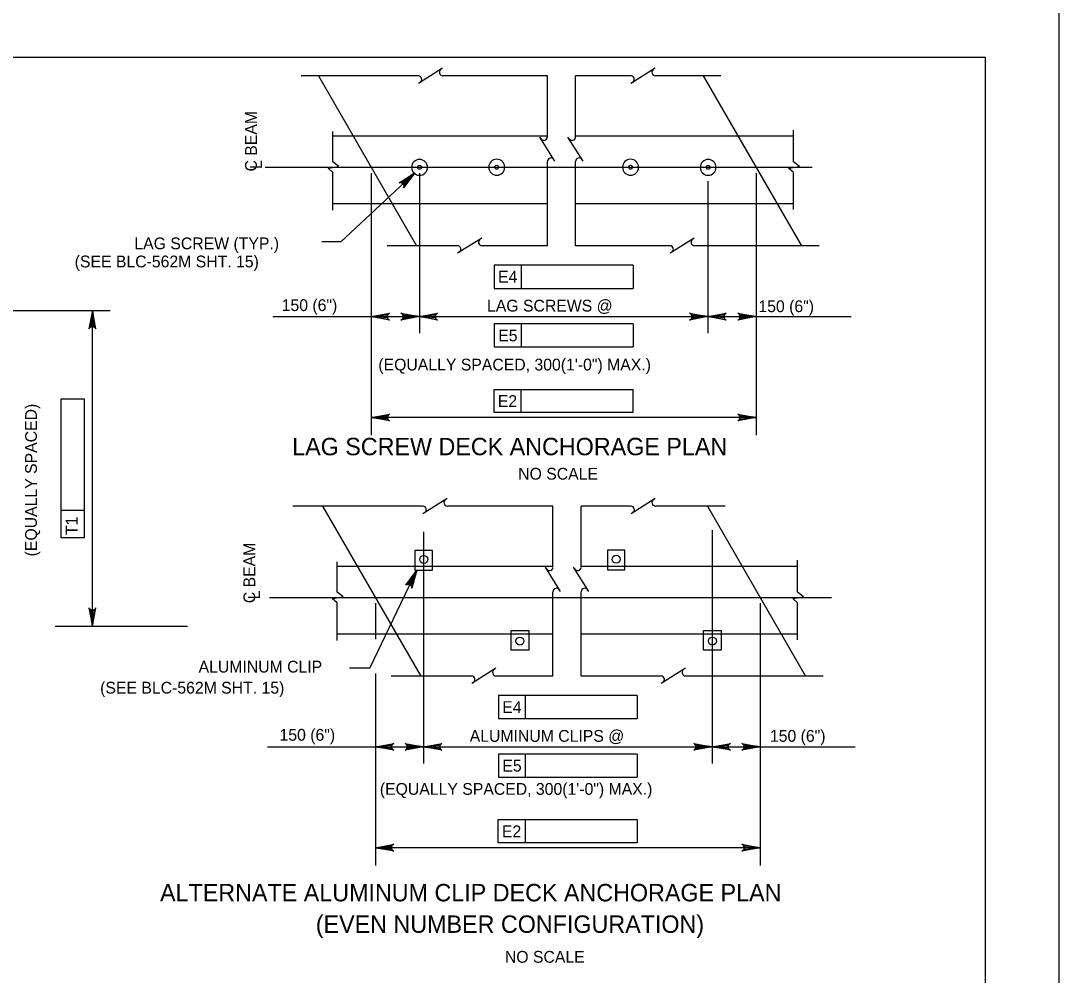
# Model space of a CAD drawing. Extents: x -13 to 81, y -176 to 0.
# Drawn here: x 57.44 to 68, y -120.08 to -110.38 of the extents above; entities that cross this region are included whole.
import ezdxf

# ---------------------------------------------------------------- set-up
doc = ezdxf.new("R2010")
doc.units = 0
for name, color, linetype in [('Level 1', 7, 'Continuous'), ('Level 2', 7, 'Continuous'), ('Level 3', 7, 'Continuous'), ('Level 4', 7, 'Continuous'), ('Level 63', 7, 'Continuous'), ('Level 8', 7, 'Continuous'), ('Level 9', 7, 'Continuous')]:
    doc.layers.add(name, color=color, linetype=linetype)

# ---------------------------------------------------------------- blocks, each defined once
blk = doc.blocks.new('B')
at = {"layer": 'Level 3'}
blk.add_circle((0, 0), 0.107, dxfattribs=at)
for start, end in [(0, 180), (180, 0)]:
    blk.add_arc((0, 0), 0.026, start, end, dxfattribs=at)

msp = doc.modelspace()

# ---------------------------------------------------------------- linework, layer by layer
at = {"layer": 'Level 1'}
msp.add_lwpolyline([(35.75, -131.25), (67.25, -131.25), (67.25, -110.75), (35.75, -110.75)], close=True, dxfattribs=at)
at = {"layer": 'Level 2'}
for p, q in [((60.466, -110.934), (61.465, -112.662)), ((64.379, -110.934), (65.378, -112.662)), ((60.508, -115.308), (61.507, -117.036)), ((64.422, -115.308), (65.42, -117.036))]:
    msp.add_line(p, q, dxfattribs=at)
at = {"layer": 'Level 3'}
for p, q in [((61.73, -110.857), (61.484, -111.012)), ((63.891, -110.857), (63.645, -111.012)), ((61.484, -110.934), (60.291, -110.934)), ((62.795, -110.934), (61.733, -110.934)), ((62.795, -111.557), (62.795, -110.934)), ((63.081, -111.557), (63.081, -110.934)), ((63.645, -110.934), (63.081, -110.934)), ((64.559, -110.934), (63.894, -110.934)), ((60.614, -111.81), (60.614, -111.501)), ((65.297, -111.81), (65.297, -111.486)), ((62.795, -111.548), (60.614, -111.548)), ((62.872, -111.803), (62.717, -111.557)), ((63.158, -111.803), (63.003, -111.557)), ((65.297, -111.548), (63.081, -111.548)), ((60.675, -111.857), (60.614, -111.81)), ((62.795, -112.662), (62.795, -111.806)), ((63.081, -112.662), (63.081, -111.806)), ((65.358, -111.857), (65.297, -111.81)), ((60.565, -111.874), (60.675, -111.857)), ((60.614, -111.918), (60.565, -111.874)), ((60.614, -112.302), (60.614, -111.918)), ((65.248, -111.874), (65.358, -111.857)), ((65.297, -111.918), (65.248, -111.874)), ((65.297, -112.295), (65.297, -111.918)), ((60.614, -112.233), (62.795, -112.233)), ((63.081, -112.233), (65.297, -112.233)), ((61.882, -112.662), (61.164, -112.662)), ((62.128, -112.584), (61.882, -112.739)), ((62.795, -112.662), (62.131, -112.662)), ((64.043, -112.662), (63.081, -112.662)), ((64.289, -112.584), (64.043, -112.739)), ((65.558, -112.662), (64.292, -112.662)), ((61.53, -115.308), (60.208, -115.308)), ((61.776, -115.231), (61.53, -115.386)), ((62.852, -115.308), (61.779, -115.308)), ((62.852, -115.931), (62.852, -115.308)), ((63.138, -115.931), (63.138, -115.308)), ((63.646, -115.308), (63.138, -115.308)), ((63.892, -115.231), (63.646, -115.386)), ((64.602, -115.308), (63.895, -115.308)), ((60.656, -116.184), (60.656, -115.875)), ((62.852, -115.922), (60.656, -115.922)), ((62.929, -116.177), (62.775, -115.931)), ((63.216, -116.177), (63.061, -115.931)), ((65.339, -115.922), (63.138, -115.922)), ((65.339, -116.184), (65.339, -115.86)), ((60.608, -116.248), (60.718, -116.231)), ((60.656, -116.292), (60.608, -116.248)), ((60.718, -116.231), (60.656, -116.184)), ((62.852, -117.036), (62.852, -116.18)), ((63.138, -117.036), (63.138, -116.18)), ((65.29, -116.248), (65.401, -116.231)), ((65.339, -116.292), (65.29, -116.248)), ((65.401, -116.231), (65.339, -116.184)), ((60.656, -116.676), (60.656, -116.292)), ((65.339, -116.669), (65.339, -116.292)), ((60.656, -116.607), (62.852, -116.607)), ((63.138, -116.607), (65.339, -116.607)), ((62.271, -116.958), (62.025, -117.113)), ((64.198, -116.958), (63.952, -117.113)), ((62.025, -117.036), (61.206, -117.036)), ((62.852, -117.036), (62.274, -117.036)), ((63.952, -117.036), (63.138, -117.036)), ((65.6, -117.036), (64.201, -117.036))]:
    msp.add_line(p, q, dxfattribs=at)
for centre in [(61.538, -115.851), (63.494, -115.849), (62.516, -116.681), (64.473, -116.681)]:
    msp.add_circle(centre, 0.0407, dxfattribs=at)
for centre, start, end in [((61.733, -110.898), 120, 270), ((63.894, -110.898), 120, 270), ((61.481, -110.971), 302.1328, 84.6714), ((63.642, -110.971), 302.1328, 84.6714), ((62.758, -111.554), 212.1328, 354.6714), ((63.045, -111.554), 212.1328, 354.6714), ((62.831, -111.806), 30, 180), ((63.117, -111.806), 30, 180), ((61.879, -112.698), 302.1328, 84.6714), ((62.131, -112.625), 120, 270), ((64.04, -112.698), 302.1328, 84.6714), ((64.292, -112.625), 120, 270), ((61.527, -115.345), 302.1328, 84.6714), ((61.779, -115.272), 120, 270), ((63.643, -115.345), 302.1328, 84.6714), ((63.895, -115.272), 120, 270), ((62.816, -115.928), 212.1328, 354.6714), ((63.102, -115.928), 212.1328, 354.6714), ((62.888, -116.18), 30, 180), ((63.175, -116.18), 30, 180), ((62.274, -116.999), 120, 270), ((64.201, -116.999), 120, 270), ((62.022, -117.072), 302.1328, 84.6714), ((63.949, -117.072), 302.1328, 84.6714)]:
    msp.add_arc(centre, 0.0364, start, end, dxfattribs=at)
at = {"layer": 'Level 4'}
for p, q in [((59.926, -111.864), (65.488, -111.864)), ((60.693, -112.621), (60.502, -112.621)), ((62.254, -112.858), (62.254, -113.095)), ((62.53, -112.858), (62.254, -112.858)), ((63.666, -112.858), (62.53, -112.858)), ((62.53, -113.095), (62.53, -112.858)), ((63.666, -112.858), (63.666, -113.095)), ((61.003, -113.034), (61.003, -114.588)), ((62.254, -113.095), (63.666, -113.095)), ((64.917, -113.034), (64.917, -114.588)), ((54.307, -113.32), (58.348, -113.32)), ((58.168, -116.53), (58.168, -113.32)), ((61.003, -113.382), (61.493, -113.382)), ((64.428, -113.382), (64.917, -113.382)), ((62.254, -113.455), (62.254, -113.691)), ((62.53, -113.455), (62.254, -113.455)), ((62.53, -113.691), (62.53, -113.455)), ((63.666, -113.455), (62.53, -113.455)), ((63.666, -113.455), (63.666, -113.691)), ((62.254, -113.691), (63.666, -113.691)), ((62.253, -114.122), (62.528, -114.122)), ((62.253, -114.358), (62.253, -114.122)), ((62.528, -114.358), (62.528, -114.122)), ((62.528, -114.122), (63.665, -114.122)), ((63.665, -114.122), (63.665, -114.358)), ((57.849, -114.219), (58.085, -114.219)), ((57.849, -115.355), (57.849, -114.219)), ((58.085, -114.219), (58.085, -115.631)), ((63.665, -114.358), (62.253, -114.358)), ((64.917, -114.408), (61.003, -114.408)), ((57.849, -115.631), (57.849, -115.355)), ((58.085, -115.355), (57.849, -115.355)), ((58.085, -115.631), (57.849, -115.631)), ((60.989, -116.956), (61.467, -115.96)), ((59.969, -116.238), (65.685, -116.238)), ((57.789, -116.53), (59.135, -116.53)), ((60.989, -116.956), (60.782, -116.956)), ((62.297, -117.233), (62.297, -117.469)), ((62.572, -117.233), (62.297, -117.233)), ((62.572, -117.469), (62.572, -117.233)), ((63.709, -117.233), (62.572, -117.233)), ((63.709, -117.233), (63.709, -117.469)), ((61.046, -117.408), (61.046, -118.962)), ((64.959, -117.408), (64.959, -118.962)), ((62.297, -117.469), (63.709, -117.469)), ((61.046, -117.756), (61.535, -117.756)), ((62.297, -117.829), (62.297, -118.065)), ((62.572, -117.829), (62.297, -117.829)), ((63.709, -117.829), (62.572, -117.829)), ((62.572, -118.065), (62.572, -117.829)), ((63.709, -117.829), (63.709, -118.065)), ((64.47, -117.756), (64.959, -117.756)), ((62.297, -118.065), (63.709, -118.065)), ((62.295, -118.496), (62.571, -118.496)), ((62.295, -118.732), (62.295, -118.496)), ((62.571, -118.732), (62.571, -118.496)), ((62.571, -118.496), (63.707, -118.496)), ((63.707, -118.496), (63.707, -118.732)), ((64.959, -118.782), (61.046, -118.782)), ((63.707, -118.732), (62.295, -118.732))]:
    msp.add_line(p, q, dxfattribs=at)
for points in [[(61.446, -111.922), (60.693, -112.621)], [(61.446, -111.922), (61.333, -112.074), (61.337, -112.057), (61.334, -112.043), (61.327, -112.032), (61.317, -112.025), (61.303, -112.02), (61.286, -112.023), (61.446, -111.922), (61.303, -112.02), (61.317, -112.025), (61.446, -111.922), (61.327, -112.032), (61.334, -112.043), (61.446, -111.922), (61.337, -112.057)], [(58.168, -113.32), (58.133, -113.507), (58.143, -113.493), (58.156, -113.485), (58.168, -113.483), (58.181, -113.485), (58.193, -113.493), (58.203, -113.507), (58.168, -113.32), (58.193, -113.493), (58.181, -113.485), (58.168, -113.32), (58.168, -113.483), (58.156, -113.485), (58.168, -113.32), (58.143, -113.493)], [(61.003, -113.382), (61.19, -113.347), (61.176, -113.357), (61.168, -113.369), (61.166, -113.382), (61.168, -113.394), (61.176, -113.407), (61.19, -113.417), (61.003, -113.382), (61.176, -113.407), (61.168, -113.394), (61.003, -113.382), (61.166, -113.382), (61.168, -113.369), (61.003, -113.382), (61.176, -113.357)], [(61.493, -113.382), (61.306, -113.417), (61.321, -113.407), (61.328, -113.394), (61.33, -113.382), (61.328, -113.369), (61.321, -113.357), (61.306, -113.347), (61.493, -113.382), (61.321, -113.357), (61.328, -113.369), (61.493, -113.382), (61.33, -113.382), (61.328, -113.394), (61.493, -113.382), (61.321, -113.407)], [(61.493, -113.382), (61.679, -113.347), (61.665, -113.357), (61.657, -113.369), (61.655, -113.382), (61.657, -113.394), (61.665, -113.407), (61.679, -113.417), (61.493, -113.382), (61.665, -113.407), (61.657, -113.394), (61.493, -113.382), (61.655, -113.382), (61.657, -113.369), (61.493, -113.382), (61.665, -113.357)], [(64.428, -113.382), (64.241, -113.417), (64.256, -113.407), (64.263, -113.394), (64.265, -113.382), (64.263, -113.369), (64.256, -113.357), (64.241, -113.347), (64.428, -113.382), (64.256, -113.357), (64.263, -113.369), (64.428, -113.382), (64.265, -113.382), (64.263, -113.394), (64.428, -113.382), (64.256, -113.407)], [(64.428, -113.382), (64.614, -113.347), (64.6, -113.357), (64.592, -113.369), (64.59, -113.382), (64.592, -113.394), (64.6, -113.407), (64.614, -113.417), (64.428, -113.382), (64.6, -113.407), (64.592, -113.394), (64.428, -113.382), (64.59, -113.382), (64.592, -113.369), (64.428, -113.382), (64.6, -113.357)], [(64.917, -113.382), (64.73, -113.417), (64.745, -113.407), (64.752, -113.394), (64.754, -113.382), (64.752, -113.369), (64.745, -113.357), (64.73, -113.347), (64.917, -113.382), (64.745, -113.357), (64.752, -113.369), (64.917, -113.382), (64.754, -113.382), (64.752, -113.394), (64.917, -113.382), (64.745, -113.407)], [(61.003, -114.408), (61.19, -114.373), (61.176, -114.383), (61.168, -114.395), (61.166, -114.408), (61.168, -114.42), (61.176, -114.433), (61.19, -114.443), (61.003, -114.408), (61.176, -114.433), (61.168, -114.42), (61.003, -114.408), (61.166, -114.408), (61.168, -114.395), (61.003, -114.408), (61.176, -114.383)], [(64.917, -114.408), (64.73, -114.443), (64.745, -114.433), (64.752, -114.42), (64.754, -114.408), (64.752, -114.395), (64.745, -114.383), (64.73, -114.373), (64.917, -114.408), (64.745, -114.383), (64.752, -114.395), (64.917, -114.408), (64.754, -114.408), (64.752, -114.42), (64.917, -114.408), (64.745, -114.433)], [(61.467, -115.96), (61.418, -116.143), (61.415, -116.126), (61.407, -116.114), (61.396, -116.107), (61.384, -116.103), (61.37, -116.105), (61.355, -116.113), (61.467, -115.96), (61.37, -116.105), (61.384, -116.103), (61.467, -115.96), (61.396, -116.107), (61.407, -116.114), (61.467, -115.96), (61.415, -116.126)], [(58.168, -116.53), (58.203, -116.344), (58.193, -116.358), (58.181, -116.366), (58.168, -116.368), (58.156, -116.366), (58.143, -116.358), (58.133, -116.344), (58.168, -116.53), (58.143, -116.358), (58.156, -116.366), (58.168, -116.53), (58.168, -116.368), (58.181, -116.366), (58.168, -116.53), (58.193, -116.358)], [(61.046, -117.756), (61.232, -117.721), (61.218, -117.731), (61.211, -117.743), (61.208, -117.756), (61.211, -117.768), (61.218, -117.781), (61.232, -117.791), (61.046, -117.756), (61.218, -117.781), (61.211, -117.768), (61.046, -117.756), (61.208, -117.756), (61.211, -117.743), (61.046, -117.756), (61.218, -117.731)], [(61.535, -117.756), (61.349, -117.791), (61.363, -117.781), (61.37, -117.768), (61.373, -117.756), (61.37, -117.743), (61.363, -117.731), (61.349, -117.721), (61.535, -117.756), (61.363, -117.731), (61.37, -117.743), (61.535, -117.756), (61.373, -117.756), (61.37, -117.768), (61.535, -117.756), (61.363, -117.781)], [(61.535, -117.756), (61.721, -117.721), (61.707, -117.731), (61.7, -117.743), (61.698, -117.756), (61.7, -117.768), (61.707, -117.781), (61.721, -117.791), (61.535, -117.756), (61.707, -117.781), (61.7, -117.768), (61.535, -117.756), (61.698, -117.756), (61.7, -117.743), (61.535, -117.756), (61.707, -117.731)], [(64.47, -117.756), (64.284, -117.791), (64.298, -117.781), (64.305, -117.768), (64.308, -117.756), (64.305, -117.743), (64.298, -117.731), (64.284, -117.721), (64.47, -117.756), (64.298, -117.731), (64.305, -117.743), (64.47, -117.756), (64.308, -117.756), (64.305, -117.768), (64.47, -117.756), (64.298, -117.781)], [(64.47, -117.756), (64.657, -117.721), (64.642, -117.731), (64.635, -117.743), (64.633, -117.756), (64.635, -117.768), (64.642, -117.781), (64.657, -117.791), (64.47, -117.756), (64.642, -117.781), (64.635, -117.768), (64.47, -117.756), (64.633, -117.756), (64.635, -117.743), (64.47, -117.756), (64.642, -117.731)], [(64.959, -117.756), (64.773, -117.791), (64.787, -117.781), (64.795, -117.768), (64.797, -117.756), (64.795, -117.743), (64.787, -117.731), (64.773, -117.721), (64.959, -117.756), (64.787, -117.731), (64.795, -117.743), (64.959, -117.756), (64.797, -117.756), (64.795, -117.768), (64.959, -117.756), (64.787, -117.781)], [(61.046, -118.782), (61.232, -118.747), (61.218, -118.757), (61.211, -118.77), (61.208, -118.782), (61.211, -118.795), (61.218, -118.807), (61.232, -118.817), (61.046, -118.782), (61.218, -118.807), (61.211, -118.795), (61.046, -118.782), (61.208, -118.782), (61.211, -118.77), (61.046, -118.782), (61.218, -118.757)], [(64.959, -118.782), (64.773, -118.817), (64.787, -118.807), (64.795, -118.795), (64.797, -118.782), (64.795, -118.77), (64.787, -118.757), (64.773, -118.747), (64.959, -118.782), (64.787, -118.757), (64.795, -118.77), (64.959, -118.782), (64.797, -118.782), (64.795, -118.795), (64.959, -118.782), (64.787, -118.807)]]:
    msp.add_lwpolyline(points, dxfattribs=at)
at = {"layer": 'Level 63'}
msp.add_lwpolyline([(34, -132), (68, -132), (68, -110), (34, -110)], close=True, dxfattribs=at)
at = {"layer": 'Level 8'}
for p, q in [((61.003, -111.923), (61.003, -113.552)), ((61.493, -111.923), (61.493, -113.552)), ((64.917, -111.923), (64.917, -113.552)), ((64.428, -112.006), (64.428, -113.552)), ((60.002, -113.382), (61.379, -113.382)), ((61.493, -113.382), (64.428, -113.382)), ((64.917, -113.382), (65.884, -113.382)), ((61.535, -115.569), (61.535, -117.926)), ((64.47, -115.554), (64.47, -117.926)), ((60.863, -115.922), (60.863, -115.922)), ((61.538, -115.851), (61.538, -115.851)), ((61.046, -116.297), (61.046, -116.663)), ((64.959, -116.297), (64.959, -117.926)), ((61.242, -116.607), (61.242, -116.607)), ((64.473, -116.681), (64.473, -116.681)), ((65.173, -116.607), (65.173, -116.607)), ((61.046, -117.012), (61.046, -117.926)), ((59.949, -117.756), (61.046, -117.756)), ((61.535, -117.756), (64.47, -117.756)), ((64.959, -117.756), (65.926, -117.756))]:
    msp.add_line(p, q, dxfattribs=at)
at = {"layer": 'Level 9'}
for p, q in [((61.627, -115.76), (61.448, -115.76)), ((61.448, -115.76), (61.448, -115.96)), ((61.627, -115.96), (61.627, -115.76)), ((63.584, -115.758), (63.405, -115.758)), ((63.405, -115.758), (63.405, -115.958)), ((63.584, -115.958), (63.584, -115.758)), ((61.448, -115.96), (61.627, -115.96)), ((63.405, -115.958), (63.584, -115.958)), ((62.426, -116.772), (62.426, -116.572)), ((62.426, -116.572), (62.605, -116.572)), ((62.605, -116.572), (62.605, -116.772)), ((64.383, -116.772), (64.383, -116.572)), ((64.383, -116.572), (64.562, -116.572)), ((64.562, -116.572), (64.562, -116.772)), ((62.605, -116.772), (62.426, -116.772)), ((64.562, -116.772), (64.383, -116.772))]:
    msp.add_line(p, q, dxfattribs=at)

# ---------------------------------------------------------------- block references
at = {"layer": 'Level 4', "xscale": 0.7559417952, "yscale": -0.7559417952, "rotation": 180}
for p in [(61.495, -111.865), (62.28, -111.864), (63.641, -111.864), (64.43, -111.865)]:
    msp.add_blockref('B', p, dxfattribs=at)

# ---------------------------------------------------------------- texts
at = {"layer": 'Level 4'}
for s, p in [('C BEAM', (59.841, -111.907)), ('L', (59.892, -111.882)), ('(EQUALLY SPACED)', (57.604, -115.82)), ('T1', (58.017, -115.603)), ('C BEAM', (59.824, -116.296)), ('L', (59.872, -116.257))]:
    msp.add_text(s, height=0.12, rotation=90, dxfattribs=at).set_placement(p)
for s, height, p in [('LAG SCREW (TYP.)', 0.12, (58.595, -112.698)), ('(SEE BLC-562M SHT. 15)', 0.12, (57.988, -112.882)), ('E4', 0.12, (62.293, -113.037)), ('150 (6")', 0.12, (60.093, -113.326)), ('LAG SCREWS @', 0.12, (62.181, -113.331)), ('150 (6")', 0.12, (64.941, -113.337)), ('E5', 0.12, (62.295, -113.634)), ('(EQUALLY SPACED, 300(1\'-0") MAX.)', 0.12, (61.076, -113.93)), ('E2', 0.12, (62.291, -114.301)), ('LAG SCREW DECK ANCHORAGE PLAN', 0.17717, (60.2, -114.792)), ('NO SCALE', 0.12, (62.498, -115.04)), ('ALUMINUM CLIP', 0.12, (59.248, -117.001)), ('(SEE BLC-562M SHT. 15)', 0.12, (58.247, -117.215)), ('E4', 0.12, (62.336, -117.412)), ('150 (6")', 0.12, (60.071, -117.694)), ('ALUMINUM CLIPS @', 0.12, (62.005, -117.705)), ('150 (6")', 0.12, (65.058, -117.705)), ('E5', 0.12, (62.337, -118.008)), ('(EQUALLY SPACED, 300(1\'-0") MAX.)', 0.12, (61.091, -118.244)), ('E2', 0.12, (62.333, -118.675)), ('ALTERNATE ALUMINUM CLIP DECK ANCHORAGE PLAN', 0.17717, (58.856, -119.327)), ('(EVEN NUMBER CONFIGURATION)', 0.17717, (60.44, -119.647)), ('NO SCALE', 0.12, (62.363, -119.951))]:
    msp.add_text(s, height=height, dxfattribs=at).set_placement(p)

doc.saveas('drawing.dxf')
